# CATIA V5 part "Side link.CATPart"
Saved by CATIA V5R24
Part number: Side link
Material "Steel": density 7860 kg/m3, Young's modulus 2e+11 Pa, Poisson ratio 0.266, thermal expansion 1.17e-05 1/K
Bounding box of the stored display mesh (mm): x -8.5 to 8.5, y -25.4 to -19.6, z 0 to 2.8
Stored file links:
  C:\Users\Jules\Documents\ECL\Watch\Side link.CATPart
  C:\Users\Jules\Documents\ECL\Watch\Midle link.CATPart
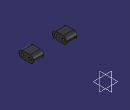
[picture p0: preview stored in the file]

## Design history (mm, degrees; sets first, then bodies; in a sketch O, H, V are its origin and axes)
Body1 (main body)
  Sketch1 on yz-plane, origin (0, 0, 0), H (0, 1, 0), V (0, 0, 1)
    line L1 (-24, 2.8) -> (-21, 2.8)
    arc A1 centre (-21, 1.4) radius 1.4 from (-21, 2.8) to (-21, 0) cw
    point P3 (-21, 1.4)
    point P4 (-21, 0)
    line L2 (-21, 0) -> (-24, 0)
    arc A2 centre (-24, 1.4) radius 1.4 from (-24, 0) to (-24, 2.8) cw
    circle A3 centre (-21, 1.4) radius 0.55
    circle A4 centre (-24, 1.4) radius 0.55
    radius A1 = 1.4
    length L2 = 3
    distance P3 V = 21
    radius A3 = 0.55
    radius A4 = 0.55
    horizontal: L1 H
    coincidence: P4 H
    tangency: A1 L1, L2 A1, A2 L1, A2 L2
  Pad1: profile Sketch1, direction (1, 0, 0), length 8.5, mirrored extent
  Sketch2 on xy-plane, origin (0, 0, 0), H (1, 0, 0), V (0, 1, 0)
    line L1 (-4.5, -19.2468) -> (4.5, -19.2468)
    line L2 (4.5, -19.2468) -> (4.5, -25.8459)
    line L3 (4.5, -25.8459) -> (-4.5, -25.8459)
    line L4 (-4.5, -25.8459) -> (-4.5, -19.2468)
    length L3 = 9
    horizontal: L1 H, L3 H
    vertical: L2 V, L4 V
    symmetry: L4 L2 V
  Pocket1: profile Sketch2, direction (0, 0, -1), length 8.5, mirrored extent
